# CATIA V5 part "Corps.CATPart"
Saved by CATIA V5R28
Part number: Corps
Bounding box of the stored display mesh (mm): x -153 to 0, y -90 to 0, z 0 to 56
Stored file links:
  Z:\Corps.CATPart
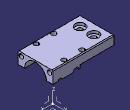
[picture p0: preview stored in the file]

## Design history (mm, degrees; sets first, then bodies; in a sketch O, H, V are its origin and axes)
AxisSystem1: origin (0, 0, 0), X (1, 0, 0), Y (0, 1, 0), Z (0, 0, 1)
Sketch1 on xy-plane, origin (0, 0, 0), H (1, 0, 0), V (0, 1, 0)
  line L1 (-153, -90) -> (-10, -90)
  line L2 (-10, -90) -> (-10, -10)
  line L3 (-10, -10) -> (-153, -10)
  line L4 (-153, -10) -> (-153, -90)
  length L3 = 143
  length L2 = 80
  horizontal: L1 H, L3 H
  vertical: L2 V, L4 V
Pad1: profile Sketch1, direction (0, 0, 1), length 56
Sketch2 on face of Pad1 from Sketch1.L3, origin (-59.643, -10, 31.2677), H (1, 0, 0), V (0, 0, -1)
  point P1 (-4.357, 3.2677)
  reference projected line E1 (49.643, 31.2677) -> (49.643, -24.7323) from edge [face of Pad1 from Sketch1.L3 | face of Pad1 from Sketch1.L2]
  reference projected line E2 (49.643, -24.7323) -> (-91.357, -24.7323) from edge [face of Chamfer1 | end face of Pad1]
  distance P1 E1 = 54
  distance P1 E2 = 28
Hole1: placed by Sketch2, at (-64, -10, 28) direction (0, -1, 0), diameter 13.835, depth 40, V-bottom angle 120, threaded "M16", thread diameter 16, thread depth 40, pitch 2
Body1 (main body)
  Chamfer1: length 2, angle 45, on edge [face of Pad1 from Sketch1.L3 | end face of Pad1]; edge [face of Pad1 from Sketch1.L4 | face of Pad1 from Sketch1.L3]; edge [start face of Pad1 | face of Pad1 from Sketch1.L3]; edge [start face of Pad1 | face of Pad1 from Sketch1.L1]; edge [start face of Pad1 | face of Pad1 from Sketch1.L4]; edge [face of Pad1 from Sketch1.L1 | face of Pad1 from Sketch1.L4]; edge [face of Pad1 from Sketch1.L4 | end face of Pad1]; edge [face of Pad1 from Sketch1.L1 | end face of Pad1]
  Sketch3 on face of Pad1 from Sketch1.L3, origin (0, -10, 0), H (-1, 0, 0), V (0, 0, 1)
    line L1 (170, 36) -> (73, 36)
    line L2 (73, 36) -> (73, 20)
    line L3 (73, 20) -> (170, 20)
    line L4 (170, 20) -> (170, 36)
    reference projected line E1 (10, 56) -> (151, 56) from edge [face of Chamfer1 | end face of Pad1]
    reference projected line E2 (153, 2) -> (153, 54) from edge [face of Pad1 from Sketch1.L4 | face of Chamfer1]
    distance E1 L1 = 20
    length L4 = 16
    distance E2 L2 = 80
    horizontal: L1 H, L3 H
    vertical: L2 V, L4 V
  Pocket1: profile Sketch3, direction (0, -1, 0), through (limit type 6)
  Sketch4 on face of Pad1 from Sketch1.L3, origin (-30.0235, -10, 29.8052), H (1, 0, 0), V (0, 0, -1)
    point P1 (3.0235, 1.8052)
    reference projected line E1 (20.0235, 29.8052) -> (20.0235, -26.1948) from edge [face of Pad1 from Sketch1.L3 | face of Pad1 from Sketch1.L2]
    reference projected line E2 (20.0235, 29.8052) -> (-120.9765, 29.8052) from edge [start face of Pad1 | face of Chamfer1]
    distance P1 E1 = 17
    distance P1 E2 = 28
  Hole2: placed by Sketch4, at (-27, -10, 28) direction (0, -1, 0), diameter 8.376, depth 40, V-bottom angle 120, threaded "M10", thread diameter 10, thread depth 12, pitch 1.5
  Sketch5 on start face of Pad1, origin (-46.2517, -16.9645, 0), H (1, 0, 0), V (0, -1, 0)
    point P1 (2.2517, 1.0355)
    reference projected line E1 (36.2517, 73.0355) -> (36.2517, -6.9645) from edge [start face of Pad1 | face of Pad1 from Sketch1.L2]
    reference projected line E2 (36.2517, -6.9645) -> (-104.7483, -6.9645) from edge [face of Chamfer1 | face of Pad1 from Sketch1.L3]
    distance P1 E1 = 34
    distance P1 E2 = 8
  Hole3: placed by Sketch5, at (-44, -18, 0) direction (0, 0, 1), diameter 11, depth 150, V-bottom angle 120
  RectPattern1: of Hole3, direction 1 instances 2, spacing 0, along start face of Pad1, direction 2 instances 2, spacing 64, along start face of Pad1
  Sketch6 on start face of Pad1, origin (-83.8817, -16.3389, 0), H (1, 0, 0), V (0, -1, 0)
    point P1 (-1.1183, 1.1611)
    reference projected line E1 (73.8817, 73.6611) -> (73.8817, -6.3389) from edge [start face of Pad1 | face of Pad1 from Sketch1.L2]
    reference projected line E2 (73.8817, -6.3389) -> (-67.1183, -6.3389) from edge [face of Chamfer1 | face of Pad1 from Sketch1.L3]
    distance P1 E1 = 75
    distance P1 E2 = 7.5
  Hole4: placed by Sketch6, at (-85, -17.5, 0) direction (0, 0, 1), diameter 11, depth 150, V-bottom angle 120
  RectPattern2: of Hole4, direction 1 instances 1, spacing 20, along start face of Pad1, direction 2 instances 2, spacing 65, along start face of Pad1
  Sketch7 on face of Pad1 from Sketch1.L2, origin (-10, -49.2861, 28.526), H (0, 1, 0), V (0, 0, 1)
    point P1 (-0.7139, -0.526)
    reference projected line E1 (39.2861, -28.526) -> (39.2861, 27.474) from edge [face of Pad1 from Sketch1.L3 | face of Pad1 from Sketch1.L2]
    reference projected line E2 (-40.7139, -28.526) -> (39.2861, -28.526) from edge [start face of Pad1 | face of Pad1 from Sketch1.L2]
    distance P1 E1 = 40
    distance P1 E2 = 28
  Hole5: placed by Sketch7, at (-10, -50, 28) direction (-1, 0, 0), diameter 50, depth 84
  Sketch8 on face of Pad1 from Sketch1.L2, origin (-10, -16.5767, 8.194), H (0, 1, 0), V (0, 0, 1)
    point P1 (-0.9233, -0.194)
    reference projected line E1 (-73.4233, -8.194) -> (6.5767, -8.194) from edge [start face of Pad1 | face of Pad1 from Sketch1.L2]
    reference projected line E2 (6.5767, -8.194) -> (6.5767, 47.806) from edge [face of Pad1 from Sketch1.L3 | face of Pad1 from Sketch1.L2]
    distance P1 E1 = 8
    distance P1 E2 = 7.5
  Hole6: placed by Sketch8, at (-10, -17.5, 8) direction (-1, 0, 0), diameter 10.106, depth 27, threaded "M12", thread diameter 12, thread depth 25, pitch 1.75
  RectPattern3: of Hole6, direction 1 instances 2, spacing 65, along face of Pad1 from Sketch1.L2 reversed, direction 2 instances 2, spacing 40, along face of Pad1 from Sketch1.L2
  Sketch9 on start face of Pad1, origin (-136.8054, -24.187, 0), H (1, 0, 0), V (0, -1, 0)
    point P1 (7.8054, 9.813)
    reference projected line E1 (126.8054, -14.187) -> (-14.1946, -14.187) from edge [face of Chamfer1 | face of Pad1 from Sketch1.L3]
    reference projected line E2 (-16.1946, -12.187) -> (-16.1946, 63.813) from edge [face of Chamfer1 | face of Pad1 from Sketch1.L4]
    distance P1 E1 = 24
    distance P1 E2 = 24
  Hole7: placed by Sketch9, at (-129, -34, 0) direction (0, 0, 1), diameter 23, depth 6
  RectPattern4: of Hole7, direction 1 instances 2, spacing 32, along face of Pad1 from Sketch1.L4, direction 2 instances 2, spacing 50, along face of Pad1 from Sketch1.L4
  Sketch10 on face of RectPattern4, origin (-129, -34, 50), H (1, 0, 0), V (0, 1, 0)
    point P1 (0, 0)
    reference projected line E1 (-24, 22) -> (-24, -54) from edge [face of Pad1 from Sketch1.L4 | face of Chamfer1]
    reference projected line E2 (119, 24) -> (-22, 24) from edge [face of Pad1 from Sketch1.L3 | face of Chamfer1]
    distance P1 E1 = 24
    distance P1 E2 = 24
  Hole8: placed by Sketch10, at (-129, -34, 50) direction (0, 0, -1), diameter 12, depth 200
  RectPattern5: of Hole8, direction 1 instances 2, spacing 32, along face of Pad1 from Sketch1.L4
  Sketch11 on face of Hole5, origin (-94, -51.7763, 11.8793), H (0, 1, 0), V (0, 0, 1)
    point P1 (1.7763, 0.1207)
    reference projected line E1 (-38.2237, -11.8793) -> (41.7763, -11.8793) from edge [start face of Pad1 | face of Pad1 from Sketch1.L2]
    reference projected line E2 (-38.2237, -11.8793) -> (-38.2237, 44.1207) from edge [face of Pad1 from Sketch1.L2 | face of Pad1 from Sketch1.L1]
    distance P1 E1 = 12
    distance P1 E2 = 40
  Hole9: placed by Sketch11, at (-94, -50, 12) direction (-1, 0, 0), diameter 7, depth 25
  RectPattern6: of Hole9, direction 1 instances 1, spacing 32, along face of Hole5, direction 2 instances 2, spacing 32, along face of Hole5 reversed
  Sketch12 on face of Pad1 from Sketch1.L3, origin (0, -10, 0), H (-1, 0, 0), V (0, 0, 1)
    line L1 (-1.3895, 28) -> (165.3716, 28)
    line L2 (165.3716, 28) -> (165.3716, -22.5842)
    line L3 (165.3716, -22.5842) -> (-1.3895, -22.5842)
    line L4 (-1.3895, -22.5842) -> (-1.3895, 28)
    reference projected line E1 (10, 0) -> (151, 0) from edge [start face of Pad1 | face of Chamfer1]
    distance E1 L1 = 28
    horizontal: L1 H, L3 H
    vertical: L2 V, L4 V
  Pocket2: profile Sketch12, direction (0, -1, 0), through (limit type 3)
